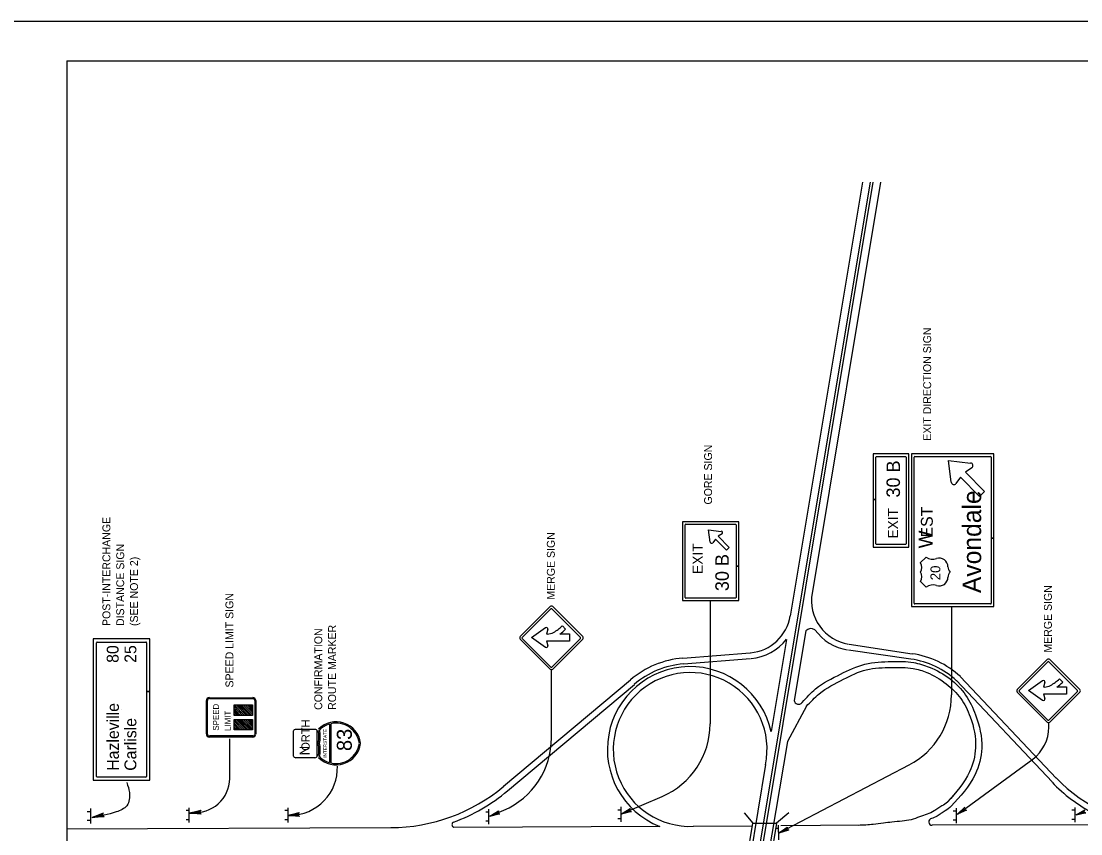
# Model space of a CAD drawing. Extents: x 640994 to 644422, y 298458 to 299646.
# Drawn here: x 643539.9 to 643942.6, y 299337 to 299645.6 of the extents above; entities that cross this region are included whole.
import ezdxf

# ---------------------------------------------------------------- set-up
doc = ezdxf.new("R2010")
doc.units = 0
for name, color, linetype in [('1', 7, 'Continuous'), ('2', 7, 'Continuous'), ('XCS-GRID-MIN', 7, 'Continuous')]:
    doc.layers.add(name, color=color, linetype=linetype)

msp = doc.modelspace()

# ---------------------------------------------------------------- linework, layer by layer
at = {"layer": '1'}
for q in [(644343.31, 299630.63), (643557.31, 299066.63)]:
    msp.add_line((643557.31, 299630.63), q, dxfattribs=at)
at = {"layer": '2'}
for p, q in [((643862.56, 299584.52), (643784.06, 299113.64)), ((643863.56, 299584.52), (643785.19, 299113.64)), ((643859.56, 299584.52), (643832.19, 299419.64)), ((643866.44, 299584.52), (643840.44, 299428.27)), ((643859.56, 299584.52), (643859.56, 299584.52)), ((643877.19, 299481.27), (643863.69, 299481.27)), ((643863.69, 299481.27), (643863.69, 299463.88)), ((643877.19, 299445.89), (643877.19, 299481.27)), ((643909.56, 299481.27), (643878.19, 299481.27)), ((643878.19, 299481.27), (643878.19, 299423.27)), ((643909.56, 299449.28), (643909.56, 299481.27)), ((643864.69, 299463.88), (643864.69, 299480.02)), ((643864.94, 299480.27), (643875.94, 299480.27)), ((643876.19, 299480.02), (643876.19, 299447.14)), ((643879.19, 299424.52), (643879.19, 299480.02)), ((643879.44, 299480.27), (643908.31, 299480.27)), ((643893.31, 299470.52), (643892.31, 299478.77)), ((643892.31, 299478.77), (643900.69, 299477.77)), ((643893.31, 299470.52), (643892.31, 299478.77)), ((643892.31, 299478.77), (643900.69, 299477.77)), ((643908.56, 299480.02), (643908.56, 299449.28)), ((643901.19, 299476.02), (643898.81, 299474.27)), ((643901.19, 299476.02), (643898.81, 299474.27)), ((643898.81, 299474.27), (643905.94, 299467.02)), ((643898.81, 299474.27), (643905.94, 299467.02)), ((643896.81, 299472.39), (643895.06, 299470.02)), ((643896.81, 299472.39), (643895.06, 299470.02)), ((643904.06, 299465.14), (643896.81, 299472.39)), ((643904.06, 299465.14), (643896.81, 299472.39)), ((643905.94, 299467.02), (643904.06, 299465.14)), ((643905.94, 299467.02), (643904.06, 299465.14)), ((643864.69, 299463.88), (643863.69, 299463.88)), ((643863.69, 299463.88), (643863.69, 299445.89)), ((643863.69, 299463.88), (643864.69, 299463.88)), ((643864.69, 299447.14), (643864.69, 299463.88)), ((643812.56, 299455.52), (643791.19, 299455.52)), ((643791.19, 299455.52), (643791.19, 299425.52)), ((643792.19, 299426.77), (643792.19, 299454.27)), ((643792.44, 299454.52), (643811.31, 299454.52)), ((643811.56, 299454.27), (643811.56, 299438.57)), ((643812.56, 299438.57), (643812.56, 299455.52)), ((643801.76, 299447.71), (643801.13, 299452.46)), ((643801.13, 299452.46), (643805.88, 299451.84)), ((643803.76, 299448.84), (643802.76, 299447.46)), ((643807.88, 299444.71), (643803.76, 299448.84)), ((643806.26, 299450.96), (643804.76, 299449.96)), ((643804.76, 299449.96), (643809.01, 299445.71)), ((643908.56, 299449.28), (643909.56, 299449.28)), ((643909.56, 299449.28), (643908.56, 299449.28)), ((643908.56, 299449.28), (643908.56, 299424.52)), ((643909.56, 299423.27), (643909.56, 299449.28)), ((643809.01, 299445.71), (643807.88, 299444.71)), ((643863.69, 299445.89), (643877.19, 299445.89)), ((643875.94, 299446.89), (643864.94, 299446.89)), ((643881.56, 299439.89), (643883.81, 299442.02)), ((643888.81, 299441.64), (643888.81, 299441.64)), ((643812.56, 299438.57), (643811.56, 299438.57)), ((643811.56, 299438.57), (643811.56, 299426.77)), ((643811.56, 299438.57), (643812.56, 299438.57)), ((643812.56, 299425.52), (643812.56, 299438.57)), ((643889.44, 299438.64), (643889.44, 299438.64)), ((643892.19, 299438.39), (643892.19, 299438.39)), ((643883.81, 299430.64), (643881.56, 299432.89)), ((643887.31, 299436.39), (643887.31, 299436.39)), ((643887.31, 299436.39), (643887.31, 299436.39)), ((643887.31, 299436.39), (643887.31, 299436.39)), ((643887.31, 299436.39), (643887.31, 299436.39)), ((643887.31, 299436.39), (643887.31, 299436.39)), ((643887.31, 299436.39), (643887.31, 299436.39)), ((643892.19, 299434.39), (643892.19, 299434.39)), ((643791.19, 299425.52), (643812.56, 299425.52)), ((643811.31, 299426.52), (643792.44, 299426.52)), ((643801.69, 299425.27), (643801.69, 299378.72)), ((643729.56, 299411.89), (643740.94, 299423.27)), ((643730.31, 299411.52), (643741.19, 299422.39)), ((643741.56, 299422.39), (643752.44, 299411.52)), ((643741.94, 299423.27), (643753.31, 299411.89)), ((643878.19, 299423.64), (643878.19, 299423.27)), ((643878.19, 299423.27), (643909.56, 299423.27)), ((643908.31, 299424.27), (643879.44, 299424.27)), ((643893.44, 299423.14), (643893.44, 299389.7)), ((643733.81, 299411.52), (643739.19, 299415.27)), ((643740.06, 299414.52), (643739.56, 299412.89)), ((643739.56, 299412.89), (643739.94, 299412.89)), ((643744.56, 299412.89), (643748.31, 299412.89)), ((643745.56, 299415.89), (643746.81, 299414.64)), ((643748.31, 299412.89), (643748.31, 299410.14)), ((643838.06, 299414.02), (643833.69, 299387.64)), ((643588.81, 299411.02), (643567.31, 299411.02)), ((643567.31, 299411.02), (643567.31, 299357.27)), ((643568.56, 299358.77), (643568.56, 299409.52)), ((643568.81, 299409.77), (643587.31, 299409.77)), ((643587.56, 299409.52), (643587.56, 299390.99)), ((643588.81, 299390.99), (643588.81, 299411.02)), ((643740.94, 299399.52), (643729.56, 299410.89)), ((643741.19, 299400.27), (643730.31, 299411.14)), ((643739.19, 299407.77), (643733.81, 299411.52)), ((643748.31, 299410.14), (643739.56, 299410.14)), ((643739.56, 299410.14), (643740.06, 299408.52)), ((643752.44, 299411.14), (643741.56, 299400.27)), ((643752.44, 299411.14), (643741.56, 299400.27)), ((643753.31, 299410.89), (643741.94, 299399.52)), ((643830.69, 299410.77), (643824.94, 299375.77)), ((643854.51, 299408.97), (643878.53, 299405.38)), ((643791.39, 299403.71), (643816.94, 299405.73)), ((643878.03, 299403.31), (643854.28, 299406.74)), ((643791.56, 299401.47), (643817.11, 299403.49)), ((643918.44, 299391.77), (643929.81, 299403.14)), ((643919.19, 299391.39), (643930.06, 299402.27)), ((643930.44, 299402.27), (643941.31, 299391.39)), ((643930.81, 299403.14), (643942.19, 299391.77)), ((643741.44, 299373.45), (643741.44, 299399.27)), ((643933.19, 299358.14), (643896.81, 299396.64)), ((643723.19, 299355.02), (643771.44, 299395.39)), ((643724.69, 299353.27), (643772.94, 299393.64)), ((643931.69, 299356.64), (643895.31, 299395.14)), ((643922.69, 299391.39), (643928.06, 299395.14)), ((643928.94, 299394.39), (643928.44, 299392.77)), ((643928.44, 299392.77), (643928.81, 299392.77)), ((643933.44, 299392.77), (643937.19, 299392.77)), ((643934.44, 299395.77), (643935.69, 299394.52)), ((643937.19, 299392.77), (643937.19, 299390.02)), ((643588.81, 299390.99), (643587.56, 299390.99)), ((643587.56, 299390.99), (643587.56, 299358.77)), ((643587.56, 299390.99), (643588.81, 299390.99)), ((643588.81, 299357.27), (643588.81, 299390.99)), ((643611.44, 299388.64), (643627.94, 299388.64)), ((643611.44, 299388.39), (643627.94, 299388.39)), ((643929.81, 299379.39), (643918.44, 299390.77)), ((643930.06, 299380.14), (643919.19, 299391.02)), ((643928.06, 299387.64), (643922.69, 299391.39)), ((643937.19, 299390.02), (643928.44, 299390.02)), ((643928.44, 299390.02), (643928.94, 299388.39)), ((643941.31, 299391.02), (643930.44, 299380.14)), ((643941.31, 299391.02), (643930.44, 299380.14)), ((643942.19, 299390.77), (643930.81, 299379.39)), ((643610.31, 299374.89), (643610.31, 299387.64)), ((643610.69, 299374.89), (643610.69, 299387.64)), ((643624.81, 299381.89), (643620.81, 299385.89)), ((643624.06, 299381.89), (643620.81, 299385.27)), ((643623.31, 299381.89), (643620.81, 299384.52)), ((643625.56, 299381.89), (643621.56, 299385.89)), ((643626.19, 299381.89), (643622.19, 299385.89)), ((643626.94, 299381.89), (643622.94, 299385.89)), ((643627.56, 299381.89), (643623.56, 299385.89)), ((643627.81, 299382.39), (643624.31, 299385.89)), ((643627.81, 299383.14), (643625.06, 299385.89)), ((643627.81, 299383.77), (643625.81, 299385.89)), ((643627.81, 299384.39), (643626.44, 299385.89)), ((643627.81, 299385.14), (643627.19, 299385.89)), ((643628.69, 299387.64), (643628.69, 299374.89)), ((643629.06, 299387.64), (643629.06, 299374.89)), ((643838.31, 299385.39), (643831.06, 299372.02)), ((643578.06, 299384.14), (643578.06, 299384.14)), ((643619.69, 299381.14), (643619.69, 299381.14)), ((643622.69, 299381.89), (643620.81, 299383.89)), ((643622.06, 299381.89), (643620.81, 299383.14)), ((643621.31, 299381.89), (643620.81, 299382.39)), ((643624.81, 299376.39), (643620.81, 299380.39)), ((643625.56, 299376.39), (643621.56, 299380.39)), ((643626.19, 299376.39), (643622.19, 299380.39)), ((643626.94, 299376.39), (643622.94, 299380.39)), ((643627.56, 299376.39), (643623.56, 299380.39)), ((643627.81, 299376.89), (643624.31, 299380.39)), ((643627.81, 299377.64), (643625.06, 299380.39)), ((643627.81, 299378.27), (643625.81, 299380.39)), ((643627.81, 299378.89), (643626.44, 299380.39)), ((643627.81, 299379.64), (643627.19, 299380.39)), ((643624.06, 299376.39), (643620.81, 299379.77)), ((643623.31, 299376.39), (643620.81, 299379.02)), ((643622.69, 299376.39), (643620.81, 299378.39)), ((643622.06, 299376.39), (643620.81, 299377.64)), ((643621.31, 299376.39), (643620.81, 299376.89)), ((643644.31, 299376.64), (643651.56, 299376.64)), ((643653.44, 299376.39), (643653.44, 299376.39)), ((643657.06, 299378.64), (643657.06, 299364.02)), ((643657.56, 299378.77), (643657.56, 299363.89)), ((643930.44, 299377.45), (643930.44, 299379.14)), ((643627.94, 299374.14), (643611.44, 299374.14)), ((643627.94, 299373.64), (643611.44, 299373.64)), ((643619.19, 299359.27), (643619.19, 299373.02)), ((643643.44, 299366.39), (643643.44, 299376.02)), ((643652.31, 299376.02), (643652.31, 299366.39)), ((643647.94, 299371.39), (643647.94, 299371.39)), ((643653.44, 299371.39), (643653.44, 299371.39)), ((643660.81, 299371.39), (643660.81, 299371.39)), ((643831.06, 299372.02), (643819.19, 299300.89)), ((643651.56, 299365.77), (643644.31, 299365.77)), ((643653.44, 299366.39), (643653.44, 299366.39)), ((643897.53, 299345.68), (643924.32, 299365.36)), ((643822.81, 299363.27), (643811.31, 299294.52)), ((643827.94, 299337.27), (643877.34, 299363.12)), ((643567.31, 299357.27), (643588.81, 299357.27)), ((643587.31, 299358.52), (643568.81, 299358.52)), ((643768.06, 299344.52), (643783.52, 299351.15)), ((643566.31, 299345.27), (643565.06, 299345.27)), ((643566.31, 299346.52), (643566.31, 299340.89)), ((643603.69, 299345.77), (643602.56, 299345.77)), ((643603.69, 299346.77), (643603.69, 299341.27)), ((643641.19, 299345.77), (643640.06, 299345.77)), ((643641.19, 299346.77), (643641.19, 299341.27)), ((643717.56, 299345.14), (643716.44, 299345.14)), ((643717.56, 299346.27), (643717.56, 299340.64)), ((643718.06, 299343.64), (643723.3, 299345.89)), ((643767.81, 299345.89), (643766.69, 299345.89)), ((643767.81, 299347.14), (643767.81, 299341.52)), ((643814.69, 299344.89), (643817.94, 299341.02)), ((643831.56, 299344.89), (643826.94, 299341.02)), ((643895.19, 299345.52), (643894.06, 299345.52)), ((643895.19, 299346.64), (643895.19, 299341.02)), ((643940.31, 299345.89), (643939.19, 299345.89)), ((643940.31, 299346.89), (643940.31, 299341.39)), ((643557.31, 299342.14), (643557.31, 299342.14)), ((643566.31, 299342.02), (643565.06, 299342.02)), ((643603.69, 299342.27), (643602.56, 299342.27)), ((643641.19, 299342.27), (643640.06, 299342.27)), ((643717.56, 299341.77), (643716.44, 299341.77)), ((643767.81, 299342.64), (643766.69, 299342.64)), ((643815.06, 299323.14), (643817.94, 299341.02)), ((643817.94, 299341.02), (643826.94, 299341.02)), ((643826.94, 299341.02), (643824.06, 299323.14)), ((643827.56, 299340.27), (643827.69, 299334.64)), ((643858.78, 299340.18), (643828.63, 299340.01)), ((643946.69, 299340.39), (643886.06, 299340.27)), ((643895.19, 299342.14), (643894.06, 299342.14)), ((643940.31, 299342.39), (643939.19, 299342.39)), ((643680.44, 299339.27), (643557.19, 299338.77)), ((643623.81, 299339.02), (643623.81, 299339.02)), ((643782.56, 299339.77), (643704.31, 299339.39)), ((643817.69, 299339.89), (643795.31, 299339.77)), ((643827.69, 299339.02), (643826.56, 299339.02))]:
    msp.add_line(p, q, dxfattribs=at)
for points in [[(643620.81, 299381.89), (643620.81, 299385.89), (643627.81, 299385.89), (643627.81, 299381.89)], [(643620.81, 299376.39), (643620.81, 299380.39), (643627.81, 299380.39), (643627.81, 299376.39)]]:
    msp.add_lwpolyline(points, close=True, dxfattribs=at)
for points in [[(643571.19, 299343.64), (643571.06, 299343.77), (643566.94, 299343.14), (643571.19, 299343.64), (643571.44, 299343.39), (643566.94, 299343.14), (643570.94, 299344.27), (643570.94, 299344.64), (643566.94, 299343.14), (643571.19, 299344.89), (643570.94, 299344.64)], [(643608.01, 299344.64), (643607.88, 299344.89), (643603.76, 299344.77), (643608.01, 299344.64), (643608.26, 299344.39), (643603.76, 299344.77), (643607.88, 299345.39), (643608.01, 299345.64), (643603.76, 299344.77), (643608.13, 299345.89), (643608.01, 299345.64)], [(643645.44, 299343.77), (643645.31, 299344.02), (643641.19, 299343.89), (643645.44, 299343.77), (643645.69, 299343.52), (643641.19, 299343.89), (643645.31, 299344.52), (643645.44, 299344.77), (643641.19, 299343.89), (643645.56, 299345.02), (643645.44, 299344.77)], [(643721.44, 299344.52), (643721.31, 299344.64), (643718.06, 299343.64), (643721.44, 299344.52), (643721.81, 299344.52), (643718.06, 299343.64), (643721.19, 299345.02), (643721.19, 299345.27), (643718.06, 299343.64), (643721.31, 299345.64), (643721.19, 299345.27)], [(643771.44, 299345.39), (643771.31, 299345.52), (643768.06, 299344.52), (643771.44, 299345.39), (643771.81, 299345.39), (643768.06, 299344.52), (643771.19, 299345.89), (643771.19, 299346.14), (643768.06, 299344.52), (643771.31, 299346.52), (643771.19, 299346.14)], [(643898.66, 299346.1), (643898.66, 299346.22), (643895.66, 299344.47), (643898.66, 299346.1), (643899.16, 299345.97), (643895.66, 299344.47), (643898.16, 299346.47), (643898.28, 299346.85), (643895.66, 299344.47), (643898.53, 299347.1), (643898.28, 299346.85)], [(643944.1, 299344.97), (643944.08, 299345.22), (643940.78, 299344.11), (643944.1, 299344.97), (643944.48, 299344.87), (643940.78, 299344.11), (643943.68, 299345.57), (643943.91, 299345.84), (643940.78, 299344.11), (643944.15, 299346.1), (643943.91, 299345.84)], [(643831.19, 299338.39), (643831.06, 299338.52), (643827.94, 299337.27), (643831.19, 299338.39), (643831.56, 299338.52), (643827.94, 299337.27), (643830.94, 299338.89), (643830.94, 299339.14), (643827.94, 299337.27), (643830.94, 299339.52), (643830.94, 299339.14)]]:
    msp.add_lwpolyline(points, dxfattribs=at)
for centre, radius, start, end in [((643864.94, 299480.02), 0.25, 90, 180), ((643875.94, 299480.02), 0.25, 0, 90), ((643879.44, 299480.02), 0.25, 90, 180), ((643900.62, 299476.82), 0.978, 303.2449, 87.1516), ((643900.62, 299476.82), 0.978, 303.2449, 87.1516), ((643908.31, 299480.02), 0.25, 0, 90), ((643894.32, 299470.59), 0.978, 184.8565, 325.522), ((643894.32, 299470.59), 0.978, 184.8565, 325.522), ((643792.44, 299454.27), 0.25, 90, 180), ((643811.31, 299454.27), 0.25, 0, 90), ((643805.9, 299451.39), 0.559, 303.2476, 87.1543), ((643802.3, 299447.84), 0.559, 184.8591, 325.5247), ((643864.94, 299447.14), 0.25, 180, 270), ((643875.94, 299447.14), 0.25, 270, 0), ((643886.37, 299445.79), 4.55, 235.4253, 288.1711), ((643888.82, 299438.38), 3.26, 0.0047, 108.548), ((643879.27, 299438.13), 2.93, 323.136, 36.864), ((643894.84, 299438.38), 2.76, 180, 226.2725), ((643879.27, 299434.61), 2.93, 323.136, 36.864), ((643888.82, 299434.36), 3.26, 251.452, 359.9953), ((643894.84, 299434.36), 2.76, 133.7275, 180), ((643886.37, 299426.95), 4.55, 71.8289, 124.5747), ((643792.44, 299426.77), 0.25, 180, 270), ((643811.31, 299426.77), 0.25, 270, 0), ((643857, 299425.58), 16.8, 170.549, 260.8199), ((643741.45, 299422.75), 0.699, 45, 135), ((643741.37, 299422.22), 0.25, 45, 135), ((643879.44, 299424.52), 0.25, 180, 270), ((643908.31, 299424.52), 0.25, 270, 0), ((643815.61, 299422.47), 16.8, 274.9998, 350.549), ((643739.5, 299414.72), 0.582, 343.7978, 121.6694), ((643739.88, 299417.56), 4.73, 269.7757, 299.8897), ((643734.18, 299427.73), 16.39, 299.437, 313.8849), ((643733.87, 299428.11), 18.68, 305.1415, 313.8892), ((643840.06, 299412.19), 2.71, 56.7513, 138.064), ((643857, 299425.58), 19.04, 215.7561, 260.8199), ((643568.81, 299409.52), 0.25, 90, 180), ((643587.31, 299409.52), 0.25, 0, 90), ((643730.08, 299411.38), 0.699, 135, 225), ((643730.48, 299411.33), 0.25, 135, 225), ((643752.25, 299411.35), 0.25, 309.2894, 45), ((643752.81, 299411.38), 0.699, 315, 45), ((643815.61, 299422.47), 19.04, 274.9998, 322.4775), ((643739.5, 299408.31), 0.582, 238.443, 16.0898), ((643873.38, 299370.94), 34.82, 47.6535, 81.4907), ((643794.13, 299368.99), 34.82, 94.5222, 130.6655), ((643794.13, 299368.99), 32.58, 94.5221, 130.7111), ((643873.38, 299371.06), 32.58, 47.6079, 81.7842), ((643930.32, 299402.63), 0.699, 45, 135), ((643930.25, 299402.1), 0.25, 45, 135), ((643741.45, 299400.02), 0.699, 225, 315), ((643741.37, 299400.43), 0.25, 225, 315), ((643741.37, 299400.43), 0.25, 225, 315), ((643794.13, 299368.99), 31.46, 12.3822, 248.4012), ((643794.13, 299368.99), 29.22, 348.5631, 272.42), ((643928.37, 299394.59), 0.582, 343.7978, 121.6694), ((643928.75, 299397.44), 4.73, 269.7757, 299.8897), ((643923.05, 299407.61), 16.39, 299.437, 313.8849), ((643922.74, 299407.98), 18.68, 305.1415, 313.8892), ((643611.44, 299387.58), 1.13, 90, 180), ((643627.94, 299387.58), 1.13, 0, 90), ((643863.44, 299389.7), 30, 297.6198, 0), ((643918.95, 299391.26), 0.699, 135, 225), ((643919.35, 299391.2), 0.25, 135, 225), ((643941.13, 299391.22), 0.25, 309.2894, 45), ((643941.69, 299391.26), 0.699, 315, 45), ((643611.44, 299387.58), 0.75, 90, 180), ((643627.94, 299387.58), 0.75, 0, 90), ((643835.29, 299387.81), 1.65, 185.8754, 324.1731), ((643928.37, 299388.18), 0.582, 238.443, 16.0898), ((643659.57, 299370.06), 9.44, 8.1301, 135), ((643659.57, 299370.06), 8.94, 106.3155, 135), ((643643.29, 299373.85), 10.28, 345.75, 14.25), ((643659.57, 299370.06), 8.94, 8.1301, 103.0131), ((643771.69, 299378.72), 30, 293.2274, 0), ((643915.44, 299377.45), 15, 306.3102, 0), ((643930.32, 299379.89), 0.699, 225, 315), ((643930.25, 299380.31), 0.25, 225, 315), ((643930.25, 299380.31), 0.25, 225, 315), ((643611.44, 299374.83), 1.13, 180, 270), ((643611.44, 299374.83), 0.75, 180, 270), ((643627.94, 299374.83), 1.13, 270, 0), ((643627.94, 299374.83), 0.75, 270, 0), ((643643.29, 299373.85), 9.78, 345.75, 14.25), ((643711.44, 299373.45), 30, 293.2859, 0), ((643643.29, 299368.79), 9.78, 345.75, 14.25), ((643659.57, 299372.58), 9.44, 225, 351.8699), ((643643.29, 299368.79), 10.28, 345.75, 14.25), ((643659.57, 299372.58), 8.94, 256.964, 351.8699), ((643659.57, 299372.58), 8.94, 225, 253.656), ((643642.07, 299362.02), 18.01, 270.3852, 1.9691), ((643568.81, 299358.77), 0.25, 180, 270), ((643587.31, 299358.77), 0.25, 270, 0), ((643605.98, 299358.25), 13.25, 270.827, 4.4), ((643974, 299396.57), 58.23, 223.3194, 242.7882), ((643974, 299396.57), 55.99, 223.3194, 270.2525), ((643680.11, 299406.47), 67.18, 270.2525, 309.9999), ((643680.11, 299406.47), 69.42, 290.3144, 309.9999), ((643704.67, 299340.4), 1.07, 115.542, 249.178), ((643886.06, 299341.48), 1.28, 97.9214, 271.8942)]:
    msp.add_arc(centre, radius, start, end, dxfattribs=at)
for centre, major_axis, start_param, end_param in [((643644.33, 299376.08), (-0.896, 0), 4.712389, 6.283185), ((643651.49, 299376.08), (-0.896, 0), 3.141593, 4.712389), ((643644.33, 299366.41), (0.896, 0), 3.141593, 4.712389), ((643651.49, 299366.41), (0.896, 0), 4.712389, 6.283185)]:
    msp.add_ellipse(centre, major_axis=major_axis, ratio=0.6, start_param=start_param, end_param=end_param, dxfattribs=at)
for points in [[(643836.69, 299386.89), (643841.81, 299392.02), (643851.31, 299397.64), (643860.56, 299401.39), (643870.69, 299402.39), (643879.06, 299402.02), (643884.94, 299400.27), (643892.94, 299395.77), (643898.81, 299389.64), (643902.56, 299382.14), (643904.94, 299369.52), (643902.44, 299359.52), (643893.31, 299347.39)], [(643838.31, 299385.39), (643843.19, 299390.14), (643852.44, 299395.64), (643861.06, 299399.27), (643870.69, 299400.14), (643878.81, 299399.77), (643884.06, 299398.27), (643891.44, 299393.89), (643896.94, 299388.39), (643900.56, 299381.39), (643902.56, 299369.64), (643900.31, 299360.52), (643891.94, 299349.14)], [(643838.31, 299385.39), (643843.19, 299390.14), (643852.44, 299395.64), (643861.06, 299399.27), (643870.69, 299400.14), (643878.81, 299399.77), (643884.06, 299398.27), (643891.44, 299393.89), (643896.94, 299388.39), (643900.56, 299381.39), (643902.56, 299369.64), (643900.31, 299360.52), (643891.94, 299349.02)], [(643580.06, 299356.39), (643581.06, 299352.64), (643580.06, 299347.64), (643576.06, 299345.27), (643566.94, 299343.14)], [(643891.94, 299349.02), (643889.81, 299347.52), (643888.19, 299346.52), (643886.81, 299345.64), (643884.19, 299344.39), (643881.31, 299343.39), (643878.06, 299342.27), (643874.69, 299341.77), (643870.81, 299341.39), (643867.56, 299341.02), (643863.69, 299340.52), (643858.19, 299340.14)], [(643893.31, 299347.39), (643891.06, 299345.64), (643889.44, 299344.64), (643887.94, 299343.64), (643885.81, 299342.77)]]:
    msp.add_spline(points, degree=3, dxfattribs=at)
at = {"layer": 'XCS-GRID-MIN'}
msp.add_lwpolyline([(643517.31, 299645.63), (644358.31, 299645.63), (644358.31, 299051.63), (643517.31, 299051.63)], close=True, dxfattribs=at)

# ---------------------------------------------------------------- texts
at = {"layer": '2'}
for s, height, rotation, p in [('EXIT DIRECTION SIGN', 3, 90, (643885.69, 299486.27)), ('GORE SIGN', 3, 90, (643802.44, 299462.02)), ('30 B', 5.125, 90, (643873.86, 299464.69)), ('Avondale', 7, 89.9998, (643904.69, 299428.39)), ('EST', 4.5, 90, (643886.31, 299449.52)), ('POST-INTERCHANGE', 3, 90, (643573.81, 299415.89)), ('EXIT', 3.875, 90, (643873.15, 299449.13)), ('MERGE SIGN', 3, 90, (643742.69, 299425.89)), ('W', 5.38, 90, (643886.31, 299445.39)), ('DISTANCE SIGN', 3, 90, (643579.06, 299415.89)), ('EXIT', 3.917, 90, (643798.94, 299435.64)), ('(SEE NOTE 2)', 3, 90, (643584.31, 299415.89)), ('30 B', 5.125, 90, (643808.82, 299429.14)), ('20', 3.75, 90, (643889.19, 299433.27)), ('MERGE SIGN', 3, 90, (643931.56, 299405.77)), ('SPEED LIMIT SIGN', 3, 90, (643620.56, 299392.52)), ('CONFIRMATION', 3, 90, (643654.31, 299384.02)), ('ROUTE MARKER', 3, 90, (643659.56, 299384.02)), ('80', 4.5, 90, (643576.94, 299401.89)), ('25', 4.5, 90, (643583.69, 299401.89)), ('Hazleville       ', 4.5, 90, (643577.06, 299360.89)), ('SPEED', 2.249, 90, (643615.06, 299376.14)), ('Carlisle       ', 4.5, 90, (643583.69, 299360.89)), ('LIMIT', 2.249, 90, (643619.56, 299376.02)), ('ORTH', 3.125, 90, (643649.56, 299368.52)), ('INTERSTATE', 1.264, 90, (643656.06, 299365.89)), ('83', 5.69, 90, (643665.56, 299368.39)), ('N', 3.75, 90, (643649.56, 299366.77))]:
    msp.add_text(s, height=height, rotation=rotation, dxfattribs=at).set_placement(p)

doc.saveas('drawing.dxf')
